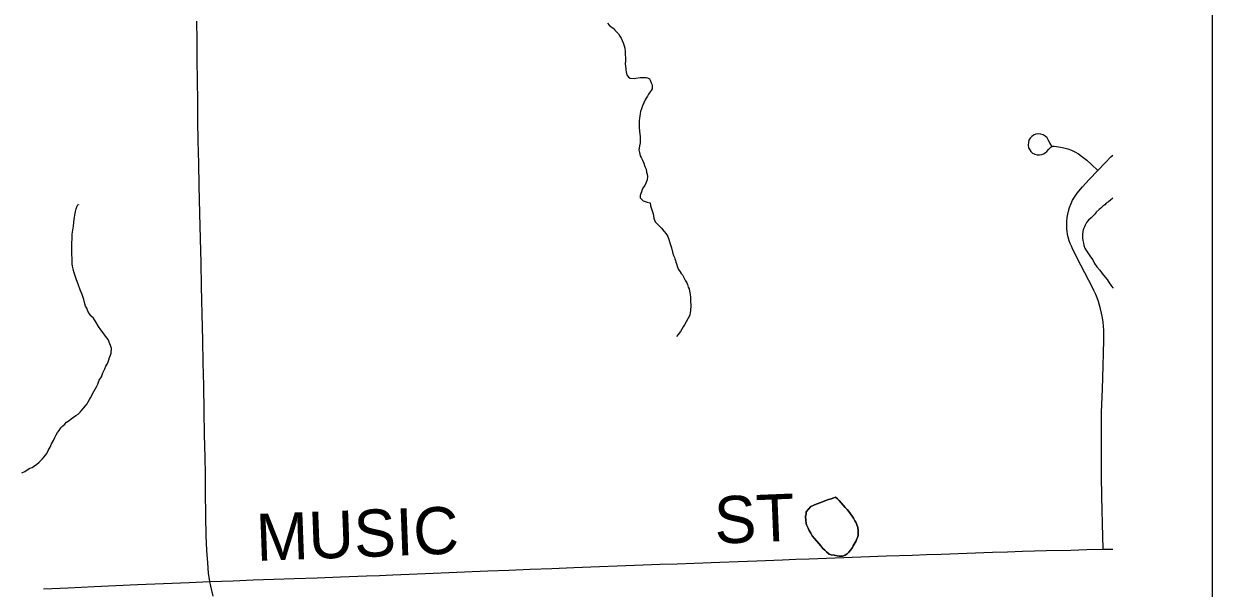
# Model space of a CAD drawing. Extents: x -11.4 to 84.1, y 11.1 to 59.
# Drawn here: x 31.731 to 33.165, y 42.991 to 43.671 of the extents above; entities that cross this region are included whole.
import ezdxf

# ---------------------------------------------------------------- set-up
doc = ezdxf.new("R2010")
doc.units = 0
for name, color, linetype in [('GM_X_Minor_Lake', 7, 'Continuous'), ('GM_X_Minor_River', 7, 'Continuous'), ('GM_X_Township_Road', 7, 'Continuous'), ('GM_X_Township_Road_Text', 7, 'Continuous'), ('SH_Data', 7, 'Continuous')]:
    doc.layers.add(name, color=color, linetype=linetype)

msp = doc.modelspace()

# ---------------------------------------------------------------- linework, layer by layer
at = {"layer": 'GM_X_Minor_Lake'}
for points in [[(32.6807, 43.0889), (32.6871, 43.092), (32.6928, 43.094), (32.6977, 43.096), (32.7022, 43.0976), (32.7052, 43.0984), (32.7086, 43.0996), (32.7105, 43.1004), (32.7128, 43.0985), (32.7151, 43.0963), (32.7175, 43.0937), (32.7198, 43.0907), (32.7221, 43.088), (32.7244, 43.0854), (32.7264, 43.0832), (32.7287, 43.0802), (32.7306, 43.0775), (32.7322, 43.0749), (32.7338, 43.0719), (32.735, 43.07), (32.7357, 43.0681), (32.7373, 43.0636), (32.7378, 43.0602), (32.7378, 43.0583), (32.7378, 43.0564), (32.7379, 43.0541), (32.7372, 43.0518), (32.7361, 43.0499), (32.7353, 43.0476), (32.7342, 43.0456), (32.7331, 43.0437), (32.732, 43.0418), (32.7309, 43.0395), (32.7287, 43.0364), (32.7264, 43.0341), (32.7246, 43.0322), (32.722, 43.0302), (32.7189, 43.029), (32.7151, 43.029), (32.7125, 43.0297), (32.709, 43.0304), (32.7052, 43.0307), (32.7029, 43.0318), (32.6995, 43.0344), (32.6975, 43.0363), (32.6952, 43.0385), (32.6929, 43.0415), (32.6902, 43.0445), (32.6875, 43.0475), (32.6851, 43.0505), (32.6824, 43.0539), (32.6805, 43.0569), (32.6785, 43.0603), (32.6773, 43.063), (32.6762, 43.0652), (32.6754, 43.0671), (32.675, 43.069), (32.6745, 43.0724), (32.6744, 43.0774), (32.6752, 43.08), (32.6751, 43.0827), (32.6807, 43.0889)], [(32.6807, 43.0889), (32.6751, 43.0827), (32.6752, 43.08), (32.6744, 43.0774), (32.6745, 43.0724), (32.675, 43.069), (32.6754, 43.0671), (32.6762, 43.0652), (32.6773, 43.063), (32.6785, 43.0603), (32.6805, 43.0569), (32.6824, 43.0539), (32.6851, 43.0505), (32.6875, 43.0475), (32.6902, 43.0445), (32.6929, 43.0415), (32.6952, 43.0385), (32.6975, 43.0363), (32.6995, 43.0344), (32.7029, 43.0318), (32.7052, 43.0307), (32.709, 43.0304), (32.7125, 43.0297), (32.7151, 43.029), (32.7189, 43.029), (32.722, 43.0302), (32.7246, 43.0322), (32.7264, 43.0341), (32.7287, 43.0364), (32.7309, 43.0395), (32.732, 43.0418), (32.7331, 43.0437)], [(32.7331, 43.0437), (32.7342, 43.0456), (32.7353, 43.0476), (32.7361, 43.0499), (32.7372, 43.0518), (32.7379, 43.0541), (32.7378, 43.0564), (32.7378, 43.0583), (32.7378, 43.0602), (32.7373, 43.0636), (32.7357, 43.0681), (32.735, 43.07), (32.7338, 43.0719), (32.7322, 43.0749), (32.7306, 43.0775), (32.7287, 43.0802), (32.7264, 43.0832), (32.7244, 43.0854), (32.7221, 43.088), (32.7198, 43.0907), (32.7175, 43.0937), (32.7151, 43.0963), (32.7128, 43.0985), (32.7105, 43.1004), (32.7086, 43.0996), (32.7052, 43.0984), (32.7022, 43.0976), (32.6977, 43.096), (32.6928, 43.094), (32.6871, 43.092), (32.6807, 43.0889)]]:
    msp.add_lwpolyline(points, dxfattribs=at)
at = {"layer": 'GM_X_Minor_River'}
msp.add_line((33.0454, 43.4612), (33.0452, 43.461), dxfattribs=at)
for points in [[(32.4354, 43.6719), (32.4374, 43.6697), (32.4397, 43.6678), (32.442, 43.666), (32.4439, 43.6637), (32.4462, 43.6615), (32.4485, 43.6592), (32.4501, 43.6566), (32.4517, 43.654), (32.4529, 43.6513), (32.454, 43.6483), (32.4552, 43.6449), (32.4561, 43.6419), (32.4565, 43.6381), (32.4571, 43.6267), (32.4567, 43.6232), (32.4568, 43.6202), (32.4572, 43.6175), (32.4573, 43.6156), (32.4577, 43.6134), (32.4581, 43.6115), (32.4585, 43.6096), (32.4604, 43.6069), (32.4627, 43.6058), (32.4673, 43.6055), (32.4696, 43.6056), (32.4745, 43.6064), (32.4775, 43.6065), (32.4798, 43.6065), (32.4817, 43.6065), (32.4836, 43.6062), (32.4859, 43.6051), (32.4867, 43.6032), (32.4879, 43.6002), (32.4891, 43.5979), (32.4891, 43.596), (32.4892, 43.593), (32.4881, 43.591), (32.4869, 43.5891), (32.4847, 43.5864), (32.4836, 43.5841), (32.4817, 43.5818), (32.4806, 43.5795), (32.4792, 43.5761), (32.4774, 43.5722), (32.4763, 43.5688), (32.4752, 43.5657), (32.4748, 43.5631), (32.4741, 43.56), (32.4738, 43.5574), (32.4735, 43.5543), (32.4735, 43.5509), (32.4736, 43.5463), (32.4741, 43.5376), (32.4745, 43.5357), (32.4746, 43.5327), (32.4746, 43.53), (32.4747, 43.5277), (32.474, 43.5243), (32.4733, 43.5212), (32.4729, 43.5193), (32.4737, 43.5159), (32.4746, 43.5121), (32.4757, 43.5099), (32.4773, 43.5068), (32.4789, 43.5031), (32.4801, 43.4993), (32.4817, 43.4959)], [(32.4817, 43.4959), (32.4825, 43.4925), (32.4833, 43.4898), (32.4837, 43.4872), (32.483, 43.483), (32.4816, 43.4792), (32.4801, 43.4761), (32.4786, 43.4742), (32.4771, 43.4715), (32.4764, 43.4688), (32.4753, 43.4665), (32.4746, 43.4642), (32.4747, 43.4615), (32.4781, 43.4578), (32.4831, 43.456), (32.4869, 43.4553), (32.4873, 43.4519), (32.489, 43.4458), (32.4902, 43.442), (32.491, 43.4367), (32.4926, 43.4326), (32.4984, 43.427), (32.5003, 43.4247), (32.5031, 43.4213), (32.5062, 43.418), (32.5081, 43.4146), (32.5097, 43.41), (32.5109, 43.4059), (32.5125, 43.4009), (32.5137, 43.396), (32.5149, 43.3919), (32.5161, 43.3896), (32.5165, 43.3877), (32.5173, 43.3858), (32.5177, 43.3839), (32.5185, 43.3817), (32.5197, 43.3779), (32.5209, 43.3749), (32.5229, 43.3722), (32.524, 43.3703), (32.5256, 43.3685), (32.5268, 43.3662), (32.528, 43.3636), (32.5295, 43.3613), (32.5311, 43.3587), (32.5319, 43.3568), (32.5327, 43.3538), (32.5339, 43.3515), (32.5343, 43.3488), (32.5347, 43.3469), (32.5351, 43.3447), (32.5355, 43.3416), (32.5356, 43.3382), (32.5356, 43.3355), (32.5357, 43.3329), (32.5357, 43.3298), (32.5354, 43.3272), (32.5354, 43.3253), (32.5351, 43.323), (32.5348, 43.3199), (32.5326, 43.3161), (32.53, 43.3119), (32.5281, 43.3084), (32.5266, 43.3057), (32.5248, 43.303), (32.5233, 43.3), (32.5207, 43.2965), (32.5187, 43.2941)], [(33.0452, 43.461), (33.0425, 43.4587), (33.0399, 43.4564), (33.0373, 43.4548), (33.0358, 43.4529), (33.0332, 43.4513), (33.0309, 43.449), (33.0287, 43.4474), (33.0253, 43.444), (33.0235, 43.4416), (33.0212, 43.4393), (33.019, 43.4374), (33.016, 43.4343), (33.0134, 43.4316), (33.0119, 43.4285), (33.0112, 43.4266), (33.0101, 43.4247), (33.0093, 43.4228), (33.009, 43.4209), (33.0087, 43.4171), (33.0087, 43.4148), (33.0087, 43.4129), (33.0092, 43.4098), (33.01, 43.4068), (33.0104, 43.4038), (33.0116, 43.4008), (33.0136, 43.3974), (33.0159, 43.394), (33.0182, 43.3902), (33.021, 43.3865), (33.0233, 43.3823), (33.026, 43.3782), (33.0295, 43.3741), (33.0326, 43.3703), (33.0361, 43.3658), (33.0384, 43.3628), (33.0408, 43.359), (33.0427, 43.356), (33.0451, 43.353), (33.0454, 43.3524)], [(31.7928, 43.4451), (31.7939, 43.4481), (31.795, 43.4512), (31.7957, 43.4531), (31.7964, 43.4535), (31.7964, 43.4531)], [(31.7282, 43.1299), (31.7316, 43.1315), (31.7346, 43.1334), (31.738, 43.1354), (31.7406, 43.1362), (31.744, 43.1385), (31.7459, 43.1397), (31.7489, 43.1424), (31.7511, 43.1444), (31.753, 43.1467), (31.7552, 43.149), (31.7567, 43.1509), (31.7582, 43.1532), (31.76, 43.1567), (31.7622, 43.1605), (31.7641, 43.1647), (31.7663, 43.1689), (31.7681, 43.1724), (31.7696, 43.1755), (31.7714, 43.1782), (31.7733, 43.1809), (31.7751, 43.1839), (31.7778, 43.1862), (31.78, 43.1886), (31.7822, 43.1909), (31.7852, 43.1928), (31.7879, 43.1948), (31.7905, 43.1967), (31.7935, 43.1987), (31.7961, 43.2006), (31.7984, 43.2029), (31.8006, 43.2053), (31.8028, 43.2076), (31.8051, 43.2106), (31.8069, 43.213), (31.8084, 43.2153), (31.8099, 43.218), (31.811, 43.2203), (31.815, 43.2279), (31.8165, 43.2306), (31.8184, 43.2333), (31.8198, 43.2367), (31.8216, 43.2413), (31.8242, 43.2456), (31.8261, 43.2505), (31.8283, 43.2551), (31.8297, 43.2582), (31.8312, 43.2609), (31.8323, 43.2636), (31.8334, 43.2662), (31.8341, 43.2689), (31.8352, 43.2716), (31.8359, 43.2739), (31.8366, 43.28), (31.8346, 43.2853), (31.8322, 43.2906), (31.8291, 43.2947), (31.8264, 43.2985), (31.8237, 43.3022), (31.8209, 43.3063), (31.8178, 43.3109), (31.8147, 43.3161), (31.8116, 43.3191), (31.8097, 43.3214), (31.8077, 43.3248), (31.8065, 43.3282), (31.805, 43.3308), (31.8041, 43.3334), (31.8029, 43.3388), (31.8009, 43.3448), (31.7985, 43.3505), (31.7965, 43.3561), (31.7938, 43.3637), (31.7922, 43.3686), (31.791, 43.372), (31.7901, 43.3758), (31.7893, 43.3788), (31.7889, 43.3819), (31.7888, 43.3849), (31.7888, 43.3887), (31.7887, 43.3925), (31.7886, 43.3967), (31.7886, 43.4013), (31.7891, 43.4176), (31.7897, 43.4226), (31.7904, 43.4271), (31.7911, 43.4317), (31.7914, 43.4351), (31.7918, 43.4382), (31.7921, 43.4405), (31.7924, 43.4431), (31.7928, 43.4451)]]:
    msp.add_lwpolyline(points, dxfattribs=at)
at = {"layer": 'GM_X_Township_Road'}
for points in [[(31.9591, 42.9811), (31.9562, 42.9932), (31.9551, 42.9987), (31.9537, 43.0086), (31.9527, 43.0212), (31.9516, 43.036), (31.9509, 43.0543), (31.9505, 43.0769), (31.95, 43.1077), (31.9497, 43.128), (31.9493, 43.1482), (31.9488, 43.176), (31.9483, 43.2039), (31.9477, 43.2349), (31.9472, 43.2624), (31.9467, 43.2899), (31.9459, 43.321), (31.9455, 43.3378), (31.9451, 43.3546), (31.9445, 43.3833), (31.9439, 43.412), (31.9431, 43.4431), (31.9426, 43.4594), (31.9422, 43.4757), (31.9417, 43.5029), (31.9411, 43.5301), (31.9408, 43.554), (31.9405, 43.5778), (31.9402, 43.6029), (31.9399, 43.6279), (31.9397, 43.6512), (31.9394, 43.6744)], [(32.9715, 43.5238), (32.9696, 43.5271), (32.9674, 43.5313), (32.9659, 43.5338), (32.9637, 43.5359), (32.9613, 43.5373), (32.9585, 43.5382), (32.9555, 43.5386), (32.9522, 43.5381), (32.9494, 43.537), (32.9474, 43.5355), (32.9454, 43.5333), (32.944, 43.5308), (32.9433, 43.5283), (32.943, 43.525), (32.9435, 43.5219), (32.9449, 43.5192), (32.9464, 43.5173), (32.9484, 43.5154), (32.9512, 43.5139), (32.9538, 43.5132), (32.9568, 43.5131), (32.9594, 43.5136), (32.9617, 43.5144), (32.9637, 43.5157), (32.9655, 43.5174), (32.9681, 43.5201), (32.9704, 43.5224), (32.9716, 43.5232), (32.973, 43.5238), (32.9745, 43.5239), (32.9773, 43.5235), (32.982, 43.5227), (32.9863, 43.5218), (32.9908, 43.5204), (32.9952, 43.5187), (32.9994, 43.5167), (33.0037, 43.5143), (33.0073, 43.5118), (33.0138, 43.5067), (33.0197, 43.5015), (33.027, 43.4943)], [(33.0335, 43.0375), (33.0328, 43.0685), (33.0325, 43.0848), (33.0321, 43.1011), (33.0318, 43.1257), (33.0315, 43.1502), (33.0316, 43.1766), (33.0318, 43.2029), (33.0327, 43.2306), (33.0335, 43.2586), (33.034, 43.2742), (33.0346, 43.2898), (33.0345, 43.2966), (33.0343, 43.3019), (33.034, 43.3068), (33.0335, 43.3115), (33.0327, 43.3166), (33.0316, 43.3223), (33.0304, 43.3275), (33.0292, 43.332), (33.0278, 43.3364), (33.0263, 43.3408), (33.0246, 43.3449), (33.0223, 43.3498), (33.0198, 43.3547), (33.0164, 43.3616), (33.0068, 43.3802), (32.9971, 43.3989), (32.9952, 43.403), (32.9938, 43.4063), (32.9927, 43.4095), (32.9914, 43.414), (32.9907, 43.4174), (32.9901, 43.4208), (32.9898, 43.4243), (32.9899, 43.4328), (32.9903, 43.4375), (32.9909, 43.4416), (32.9916, 43.4454), (32.993, 43.4497), (32.995, 43.4547), (32.9967, 43.4584), (32.999, 43.4624), (33.0024, 43.4672), (33.0085, 43.4747), (33.0169, 43.4837), (33.027, 43.4943), (33.036, 43.5037), (33.043, 43.5108), (33.0454, 43.5129)], [(31.9551, 42.9987), (31.9832, 42.9996), (32.0075, 43.0005), (32.0322, 43.0013), (32.0569, 43.0021), (32.0849, 43.0032), (32.113, 43.0043), (32.1441, 43.0054), (32.1601, 43.006), (32.1761, 43.0066), (32.2054, 43.0078), (32.2346, 43.009), (32.2626, 43.0102), (32.2906, 43.0114), (32.3162, 43.0125), (32.3417, 43.0135), (32.3682, 43.0145), (32.3946, 43.0156), (32.4257, 43.0168), (32.4467, 43.0176), (32.4678, 43.0184), (32.4988, 43.0194), (32.5193, 43.0201), (32.5398, 43.0208), (32.5708, 43.022), (32.5931, 43.0229), (32.6154, 43.0237), (32.6464, 43.0249), (32.6626, 43.0255), (32.6788, 43.0261), (32.7099, 43.0273), (32.7409, 43.0285), (32.772, 43.0295), (32.803, 43.0305), (32.8205, 43.0311), (32.838, 43.0317), (32.869, 43.0328), (32.9001, 43.0339), (32.9181, 43.0345), (32.9361, 43.0352), (32.9653, 43.0359), (32.9944, 43.0366), (33.014, 43.0371), (33.0335, 43.0375), (33.0454, 43.0377)], [(31.7544, 42.9898), (31.7843, 42.9911), (31.8153, 42.9926), (31.8417, 42.9938), (31.868, 42.995), (31.899, 42.9962), (31.9301, 42.9974), (31.9551, 42.9987)]]:
    msp.add_lwpolyline(points, dxfattribs=at)
at = {"layer": 'SH_Data'}
msp.add_line((33.1653, 47.5483), (33.1653, 40.5483), dxfattribs=at)

# ---------------------------------------------------------------- texts
at = {"layer": 'GM_X_Township_Road_Text'}
for s, rotation, p in [('ST', 2.335, (32.5652, 43.0441)), ('MUSIC', 2.1612, (32.0119, 43.0233))]:
    msp.add_text(s, height=0.05682, rotation=rotation, dxfattribs=at).set_placement(p)

doc.saveas('drawing.dxf')
